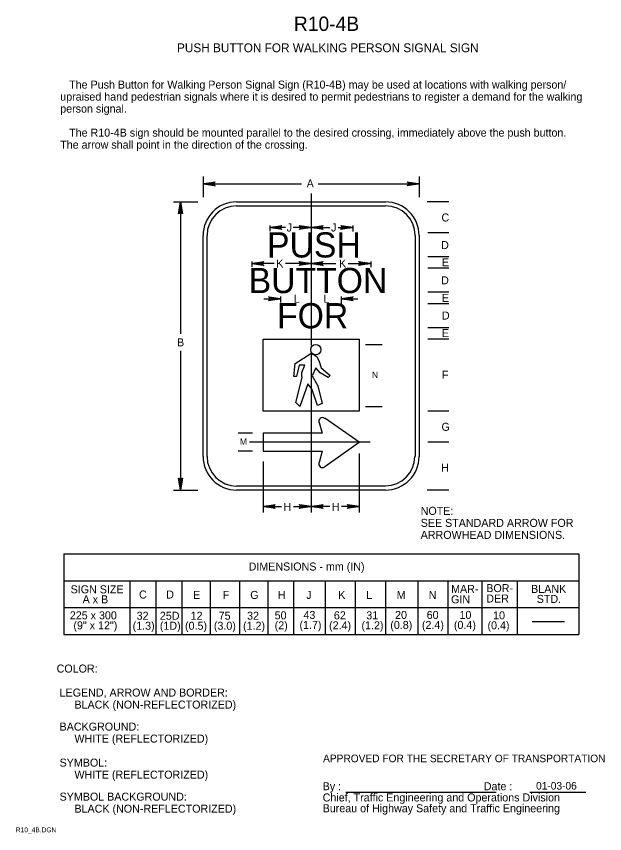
# Model space of a CAD drawing. Extents: x 0.013 to 0.196, y 0.004 to 0.259.
import ezdxf

# ---------------------------------------------------------------- set-up
doc = ezdxf.new("R2010")
doc.units = 0
for name, color, linetype in [('1', 7, 'Continuous'), ('3', 7, 'Continuous'), ('4', 7, 'Continuous')]:
    doc.layers.add(name, color=color, linetype=linetype)

# ---------------------------------------------------------------- blocks, each defined once
blk = doc.blocks.new('RARROW')
at = {"layer": '3'}
for p, q in [((-2.156, 0.28500000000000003), (-2.2665, 0.384625)), ((-2.2665, 0.384625), (0, 0)), ((0, 0), (-2.2665, -0.379125)), ((-2.156, 0.28500000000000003), (-2.075625, 0.12075)), ((0, 0), (-2.156, 0.28500000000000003)), ((-2.14975, -0.2705), (0, 0)), ((-2.075625, 0.12075), (0, 0)), ((0, 0), (-2.074, -0.108)), ((-2.2665, -0.379125), (-2.14975, -0.2705)), ((-2.074, -0.108), (-2.14975, -0.2705))]:
    blk.add_line(p, q, dxfattribs=at)

msp = doc.modelspace()

# ---------------------------------------------------------------- linework, layer by layer
at = {"layer": '1'}
for p, q in [((0.11543984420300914, 0.01694517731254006), (0.1624214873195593, 0.01694517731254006)), ((0.17295324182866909, 0.01694517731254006), (0.1905000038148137, 0.01694517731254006))]:
    msp.add_line(p, q, dxfattribs=at)
at = {"layer": '3'}
for p, q in [((0.07087500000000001, 0.209125), (0.07087500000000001, 0.20275)), ((0.07087500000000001, 0.206875), (0.10162500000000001, 0.206875)), ((0.106875, 0.206875), (0.138375, 0.206875)), ((0.138375, 0.209125), (0.138375, 0.20275)), ((0.104625, 0.203875), (0.104625, 0.1565)), ((0.061625, 0.20125), (0.06925, 0.20125)), ((0.063875, 0.20125), (0.063875, 0.16)), ((0.081375, 0.20125), (0.12787500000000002, 0.20125)), ((0.081375, 0.2), (0.12787500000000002, 0.2)), ((0.147625, 0.20125), (0.140875, 0.20125)), ((0.09175, 0.193875), (0.09175, 0.192125)), ((0.096625, 0.19325), (0.09175, 0.19325)), ((0.104625, 0.19325), (0.099, 0.19325)), ((0.104625, 0.19325), (0.1105, 0.19325)), ((0.113125, 0.19325), (0.11762500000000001, 0.19325)), ((0.11762500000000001, 0.193875), (0.11762500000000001, 0.192)), ((0.147625, 0.19162500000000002), (0.141125, 0.19162500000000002)), ((0.07087500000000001, 0.12175), (0.07087500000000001, 0.19075)), ((0.072125, 0.12175), (0.072125, 0.19075)), ((0.137125, 0.19075), (0.137125, 0.12175)), ((0.138375, 0.19075), (0.138375, 0.12175)), ((0.147625, 0.184125), (0.141125, 0.184125)), ((0.08612500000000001, 0.182625), (0.08612500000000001, 0.181)), ((0.093125, 0.182), (0.08612500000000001, 0.182)), ((0.104625, 0.182), (0.096625, 0.182)), ((0.104625, 0.182), (0.112375, 0.182)), ((0.11625, 0.182), (0.12325, 0.182)), ((0.12325, 0.182625), (0.12325, 0.180875)), ((0.147625, 0.1805), (0.141125, 0.1805)), ((0.095125, 0.17175), (0.095125, 0.169875)), ((0.114, 0.17175), (0.114, 0.16875)), ((0.147625, 0.17300000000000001), (0.141125, 0.17300000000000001)), ((0.089875, 0.171), (0.095125, 0.171)), ((0.114, 0.171), (0.11925000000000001, 0.171)), ((0.147625, 0.169375), (0.141125, 0.169375)), ((0.147625, 0.161875), (0.141125, 0.161875)), ((0.089625, 0.135875), (0.089625, 0.15837500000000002)), ((0.089625, 0.15837500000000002), (0.11962500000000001, 0.15837500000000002)), ((0.11962500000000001, 0.15837500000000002), (0.11962500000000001, 0.135875)), ((0.147625, 0.15837500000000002), (0.141125, 0.15837500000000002)), ((0.121625, 0.15675), (0.12687500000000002, 0.15675)), ((0.063875, 0.15475), (0.063875, 0.11125)), ((0.104625, 0.15425), (0.104625, 0.10425)), ((0.11962500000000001, 0.135875), (0.089625, 0.135875)), ((0.121625, 0.137375), (0.12687500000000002, 0.137375)), ((0.147625, 0.135875), (0.141125, 0.135875)), ((0.11962500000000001, 0.12625), (0.108875, 0.13375)), ((0.107125, 0.132375), (0.108125, 0.129)), ((0.08637500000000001, 0.129), (0.081875, 0.129)), ((0.089625, 0.129), (0.089625, 0.123375)), ((0.108125, 0.129), (0.089625, 0.129)), ((0.123125, 0.12625), (0.085375, 0.12625)), ((0.108875, 0.11862500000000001), (0.11962500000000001, 0.12625)), ((0.147625, 0.12625), (0.141125, 0.12625)), ((0.08637500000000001, 0.123375), (0.081875, 0.123375)), ((0.089625, 0.123375), (0.108125, 0.123375)), ((0.108125, 0.123375), (0.107125, 0.11987500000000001)), ((0.11962500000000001, 0.122625), (0.11962500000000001, 0.10425)), ((0.089625, 0.120125), (0.089625, 0.10425)), ((0.12787500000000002, 0.1125), (0.081375, 0.1125)), ((0.061625, 0.11125), (0.06925, 0.11125)), ((0.12787500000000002, 0.11125), (0.081375, 0.11125)), ((0.147625, 0.11125), (0.140875, 0.11125)), ((0.089625, 0.106125), (0.095375, 0.106125)), ((0.099125, 0.106125), (0.104625, 0.106125)), ((0.1105, 0.106125), (0.104625, 0.106125)), ((0.11962500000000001, 0.106125), (0.114125, 0.106125)), ((0.027375, 0.091375), (0.027375, 0.066125)), ((0.027412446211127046, 0.09136379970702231), (0.18830555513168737, 0.09136379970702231)), ((0.18825, 0.091375), (0.18825, 0.066125)), ((0.18830555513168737, 0.08275), (0.027430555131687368, 0.08275)), ((0.04802715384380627, 0.08275), (0.04802715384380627, 0.066125)), ((0.056125, 0.08275), (0.056125, 0.066125)), ((0.06425, 0.08275), (0.06425, 0.066125)), ((0.073125, 0.08275), (0.073125, 0.066125)), ((0.08225, 0.08275), (0.08225, 0.066125)), ((0.091125, 0.08275), (0.091125, 0.066125)), ((0.099125, 0.08275), (0.099125, 0.066125)), ((0.109, 0.08275), (0.109, 0.066125)), ((0.11837500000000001, 0.08275), (0.11837500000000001, 0.066125)), ((0.12787500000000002, 0.08275), (0.12787500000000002, 0.066125)), ((0.138, 0.08275), (0.138, 0.066125)), ((0.14740215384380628, 0.08275), (0.14740215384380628, 0.066125)), ((0.15799641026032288, 0.08275), (0.15799641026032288, 0.066125)), ((0.1689964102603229, 0.08275), (0.1689964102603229, 0.066125)), ((0.027412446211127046, 0.07461379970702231), (0.18830555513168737, 0.07461379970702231)), ((0.183780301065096, 0.07004645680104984), (0.173655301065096, 0.07004645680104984)), ((0.027412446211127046, 0.06611379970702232), (0.18830555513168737, 0.06611379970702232))]:
    msp.add_line(p, q, dxfattribs=at)
msp.add_lwpolyline([(0.110625, 0.147), (0.11, 0.146375), (0.1075, 0.147875), (0.106125, 0.149375), (0.105, 0.146875), (0.10675, 0.14375000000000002), (0.108125, 0.13825), (0.106625, 0.137625), (0.104875, 0.142875), (0.10362500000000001, 0.144375), (0.101125, 0.137375), (0.099875, 0.138625), (0.10187500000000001, 0.146375), (0.10175000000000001, 0.146875), (0.10175000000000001, 0.14725), (0.10175000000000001, 0.1475), (0.10175000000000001, 0.14775), (0.10175000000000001, 0.148), (0.10262500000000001, 0.15025), (0.100875, 0.15025), (0.100125, 0.14675), (0.09925, 0.14675), (0.099625, 0.15075), (0.1045, 0.153875), (0.105625, 0.1535), (0.106375, 0.153), (0.107125, 0.151375), (0.10775, 0.149375)], close=True, dxfattribs=at)
for centre, radius, start, end in [((0.08137499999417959, 0.19075000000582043), 0.010499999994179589, 90, 180), ((0.08137500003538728, 0.19074999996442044), 0.009250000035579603, 90, 180), ((0.12787500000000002, 0.19075), 0.0105, 0, 90), ((0.12787499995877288, 0.19074999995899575), 0.009250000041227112, 0, 90), ((0.10820068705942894, 0.13266658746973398), 0.0012000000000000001, 54.70583055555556, 198.19147500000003), ((0.081375, 0.12175), 0.0105, 180, 270), ((0.08137500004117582, 0.1217500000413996), 0.009250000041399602, 180, 270), ((0.1278750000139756, 0.12175), 0.010499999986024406, 270, 0), ((0.1278750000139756, 0.12175), 0.009199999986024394, 270, 0), ((0.10820068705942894, 0.11946658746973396), 0.0012000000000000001, 161.808525, 305.2941694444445)]:
    msp.add_arc(centre, radius, start, end, dxfattribs=at)
msp.add_ellipse((0.10608658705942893, 0.15509028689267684), major_axis=(-3.006792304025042e-19, -0.0016368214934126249), ratio=0.9570312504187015, dxfattribs=at)

# ---------------------------------------------------------------- block references
at = {"layer": '3', "xscale": 0.0016545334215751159, "yscale": 0.0016366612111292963}
for p, rotation in [((0.07087500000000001, 0.206875), 180), ((0.063875, 0.20125), 90), ((0.09175, 0.19325), 180), ((0.104625, 0.19325), 180), ((0.08612500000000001, 0.182), 180), ((0.104625, 0.182), 180), ((0.114, 0.171), 180), ((0.063875, 0.11125), -90), ((0.089625, 0.106125), 180), ((0.104625, 0.106125), 180)]:
    msp.add_blockref('RARROW', p, dxfattribs=dict(at, rotation=rotation))
for p in [(0.138375, 0.206875), (0.104625, 0.19325), (0.11762500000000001, 0.19325), (0.104625, 0.182), (0.12325, 0.182), (0.095125, 0.171), (0.104625, 0.106125), (0.11962500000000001, 0.106125)]:
    msp.add_blockref('RARROW', p, dxfattribs=at)

# ---------------------------------------------------------------- texts
at = {"layer": '1'}
for s, height, p in [('R10-4B', 0.0045000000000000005, (0.09925, 0.254625)), ('PUSH BUTTON FOR WALKING PERSON SIGNAL SIGN', 0.00275025, (0.06275, 0.248)), ('COLOR:', 0.0024997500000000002, (0.025125, 0.05425)), (' LEGEND, ARROW AND BORDER:', 0.0024997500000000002, (0.025125, 0.04675)), ('      BLACK (NON-REFLECTORIZED)', 0.0024997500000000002, (0.025125, 0.043000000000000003)), (' BACKGROUND:', 0.0024997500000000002, (0.025125, 0.036125)), ('      WHITE (REFLECTORIZED)', 0.0024997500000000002, (0.025125, 0.032375)), ('APPROVED FOR THE SECRETARY OF TRANSPORTATION', 0.0023752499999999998, (0.108375, 0.02625)), (' SYMBOL:', 0.0024997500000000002, (0.025125, 0.024875)), ('      WHITE (REFLECTORIZED)', 0.0024997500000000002, (0.025125, 0.021125)), ('By :                                                Date :', 0.0024997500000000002, (0.10825, 0.0175)), (' SYMBOL BACKGROUND:', 0.0024997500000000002, (0.025125, 0.01425)), ('Chief, Traffic Engineering and Operations Division', 0.0024997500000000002, (0.10825, 0.014)), ('      BLACK (NON-REFLECTORIZED)', 0.0024997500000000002, (0.025125, 0.0105)), ('Bureau of Highway Safety and Traffic Engineering', 0.0024997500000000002, (0.10825, 0.010625)), ('R10_4B.DGN', 0.0015, (0.012375, 0.004375))]:
    msp.add_text(s, height=height, dxfattribs=at).set_placement(p)
at = {"layer": '3'}
for s, height, p in [('   The Push Button for Walking Person Signal Sign (R10-4B) may be used at locations with walking person/', 0.0024997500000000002, (0.02625, 0.236625)), ('upraised hand pedestrian signals where it is desired to permit pedestrians to register a demand for the walking', 0.0024997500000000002, (0.02625, 0.232875)), ('person signal.', 0.0024997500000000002, (0.02625, 0.229125)), ('   The R10-4B sign should be mounted parallel to the desired crossing, immediately above the push button.', 0.0024997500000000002, (0.02625, 0.22162500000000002)), ('The arrow shall point in the direction of the crossing.', 0.0024997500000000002, (0.02625, 0.217875)), ('A', 0.0024997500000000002, (0.10325000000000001, 0.20575000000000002)), ('C', 0.0024997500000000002, (0.145375, 0.195125)), ('J', 0.0024997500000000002, (0.097, 0.192)), ('J', 0.0024997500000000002, (0.110875, 0.192)), ('PUSH', 0.007879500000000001, (0.090875, 0.183875)), ('D', 0.0024997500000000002, (0.14525, 0.1865)), ('K', 0.0024997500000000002, (0.09375, 0.18075)), ('K', 0.0024997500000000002, (0.113375, 0.18075)), ('E', 0.0024997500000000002, (0.1455, 0.181125)), ('BUTTON', 0.007879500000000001, (0.085125, 0.17275000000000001)), ('D', 0.0024997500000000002, (0.14525, 0.17550000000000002)), ('L', 0.0024997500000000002, (0.09925, 0.16975)), ('L', 0.0024997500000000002, (0.1085, 0.16975)), ('E', 0.0024997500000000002, (0.1455, 0.17)), ('FOR', 0.007879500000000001, (0.094, 0.16175)), ('D', 0.0024997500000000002, (0.1455, 0.1645)), ('E', 0.0024997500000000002, (0.1455, 0.159)), ('B', 0.0024997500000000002, (0.06275, 0.156125)), ('N', 0.0019995, (0.123625, 0.14625)), ('F', 0.0024997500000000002, (0.1455, 0.146)), ('G', 0.0024997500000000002, (0.145375, 0.12975)), ('M', 0.0019995, (0.082375, 0.12537500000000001)), ('H', 0.0024997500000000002, (0.14525, 0.117)), ('H', 0.0024997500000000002, (0.096, 0.10475)), ('H', 0.0024997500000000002, (0.111125, 0.10475)), ('NOTE:', 0.0024997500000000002, (0.138875, 0.10350000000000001)), ('SEE STANDARD ARROW FOR', 0.0024997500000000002, (0.138875, 0.09975)), ('ARROWHEAD DIMENSIONS.', 0.0024997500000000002, (0.138875, 0.096)), ('DIMENSIONS - mm (IN)', 0.0024997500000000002, (0.085125, 0.08612500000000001)), ('BOR-', 0.0024997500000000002, (0.15937500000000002, 0.079375)), ('SIGN SIZE', 0.0024997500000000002, (0.029500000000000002, 0.079)), ('C', 0.0025005, (0.050875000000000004, 0.077375)), ('D', 0.0025005, (0.059375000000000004, 0.077375)), ('E', 0.0025005, (0.06775, 0.07725)), ('F', 0.0025005, (0.077, 0.07725)), ('G', 0.0025005, (0.085625, 0.07725)), ('H', 0.0025005, (0.09425, 0.07725)), ('J', 0.0025005, (0.10312500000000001, 0.07725)), ('K', 0.0025005, (0.113125, 0.07725)), ('L', 0.0025005, (0.121875, 0.07725)), ('M', 0.0025005, (0.131375, 0.07725)), ('N', 0.0025005, (0.141375, 0.07725)), ('MAR-', 0.0024997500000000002, (0.148375, 0.079125)), ('BLANK', 0.0024997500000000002, (0.173375, 0.079125)), ('A x B', 0.0024997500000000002, (0.03325, 0.075875)), ('GIN', 0.0024997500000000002, (0.148375, 0.075875)), ('DER', 0.0024997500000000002, (0.15937500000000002, 0.076125)), ('STD.', 0.0024997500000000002, (0.175125, 0.076)), ('225 x 300', 0.0024997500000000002, (0.02925, 0.07087500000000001)), ('32', 0.0024997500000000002, (0.050125, 0.07075000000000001)), ('25D', 0.0024997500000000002, (0.057375, 0.07075000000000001)), ('12', 0.0024997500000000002, (0.067, 0.07075000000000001)), ('75', 0.0024997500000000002, (0.07575, 0.07075000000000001)), ('32', 0.0024997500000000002, (0.084625, 0.07075000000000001)), ('50', 0.0024997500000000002, (0.09325, 0.07087500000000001)), ('43', 0.0024997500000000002, (0.10225000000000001, 0.07100000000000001)), ('62', 0.0024997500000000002, (0.11175, 0.07087500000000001)), ('31', 0.0024997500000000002, (0.121875, 0.07087500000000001)), ('20', 0.0024997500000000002, (0.130875, 0.07100000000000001)), ('60', 0.0024997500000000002, (0.14075000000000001, 0.07100000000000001)), ('10', 0.0024997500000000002, (0.151, 0.07100000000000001)), ('10', 0.0024997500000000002, (0.1615, 0.07087500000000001)), ('(9" x 12")', 0.0024997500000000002, (0.030375, 0.06775)), ('(1.3)', 0.0024997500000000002, (0.048875, 0.067625)), ('(1D)', 0.0024997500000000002, (0.057375, 0.067625)), ('(0.5)', 0.0024997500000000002, (0.06525, 0.067625)), ('(3.0)', 0.0024997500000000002, (0.07425, 0.067625)), ('(1.2)', 0.0024997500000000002, (0.083375, 0.067625)), ('(2)', 0.0024997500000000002, (0.09325, 0.06775)), ('(1.7)', 0.0024997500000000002, (0.101, 0.067875)), ('(2.4)', 0.0024997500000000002, (0.11025, 0.06775)), ('(1.2)', 0.0024997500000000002, (0.120375, 0.06775)), ('(0.8)', 0.0024997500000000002, (0.129375, 0.067875)), ('(2.4)', 0.0024997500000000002, (0.13925, 0.067875)), ('(0.4)', 0.0024997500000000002, (0.14925, 0.067875)), ('(0.4)', 0.0024997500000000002, (0.15975, 0.06775))]:
    msp.add_text(s, height=height, dxfattribs=at).set_placement(p)
at = {"layer": '4'}
msp.add_text('01-03-06', height=0.0023752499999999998, dxfattribs=at).set_placement((0.17492430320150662, 0.017702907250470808))

doc.saveas('drawing.dxf')
